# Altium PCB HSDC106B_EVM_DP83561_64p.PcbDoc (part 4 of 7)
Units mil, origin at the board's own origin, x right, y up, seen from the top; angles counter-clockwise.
Board outline 8750.24 x 6394.7 mil, 6 copper layers (Top Layer, GND1, SIG1, SIG2, GND2, Bottom Layer), stack 60.4 mil thick; 472 components, 324 nets, 1622 pads, 1086 vias.
Unrouted connection lines stored in the file: 1.
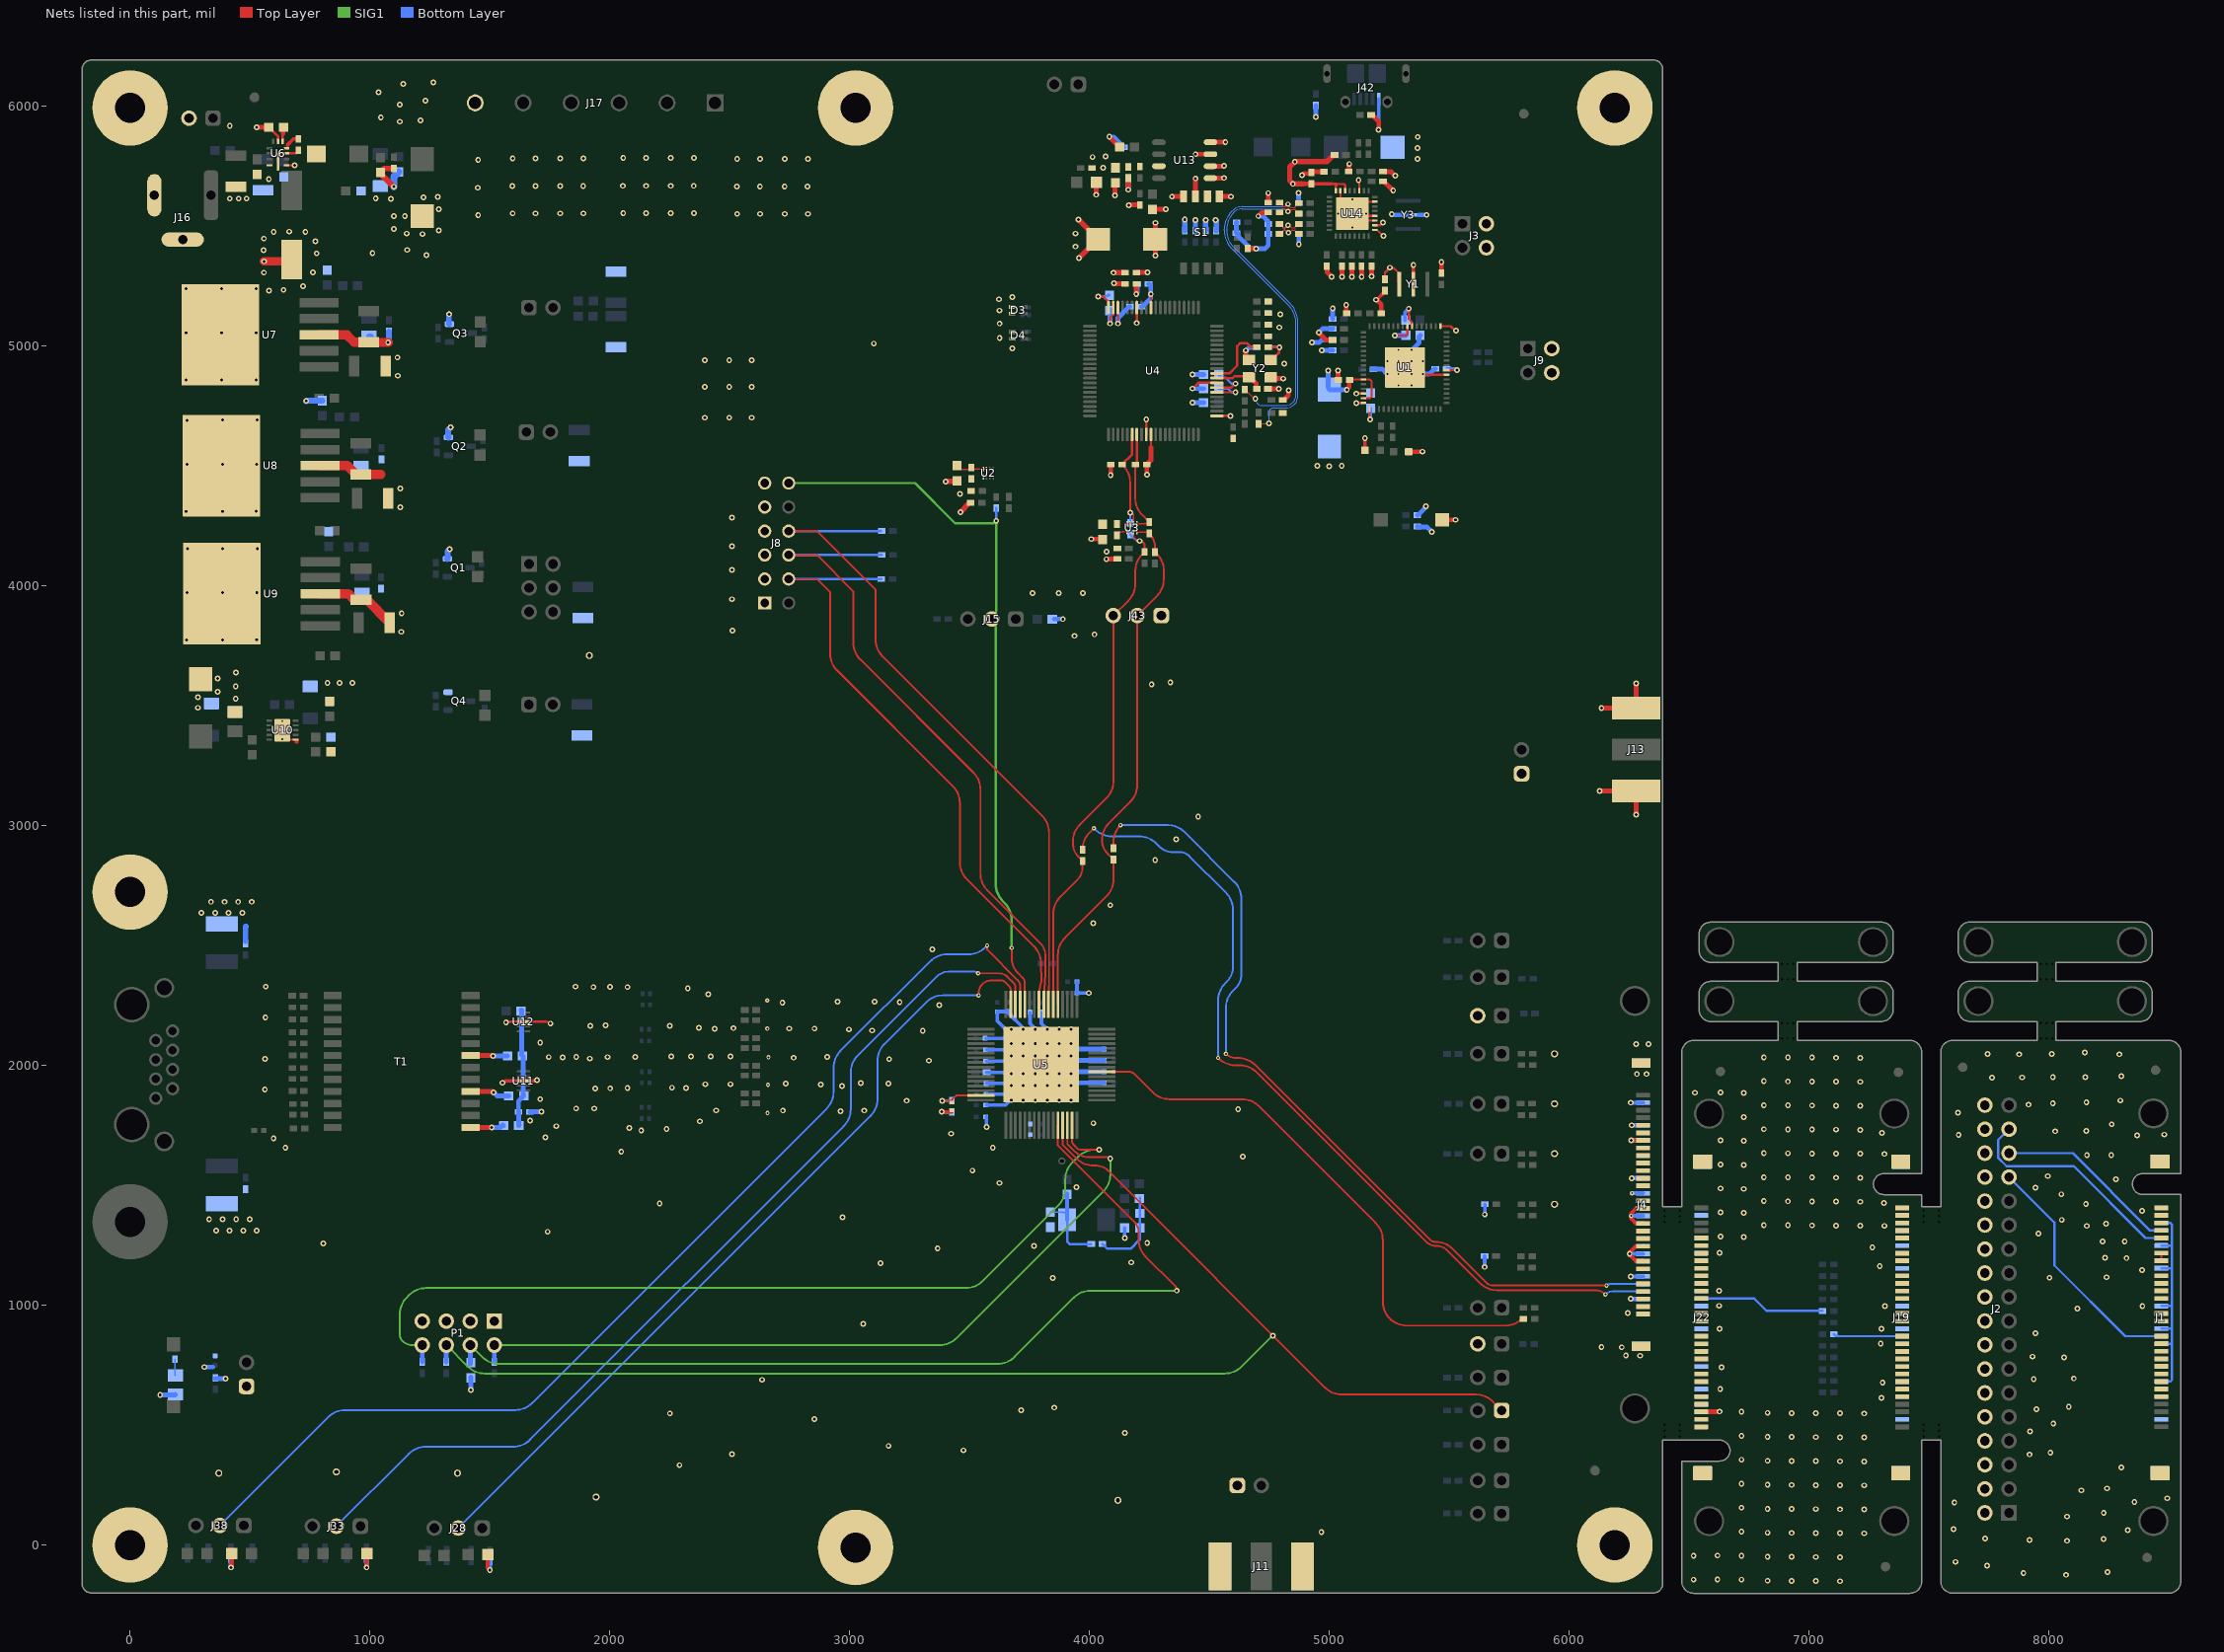
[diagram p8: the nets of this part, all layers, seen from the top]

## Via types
v1: diameter 24, hole 12, Top Layer to Bottom Layer, tented both sides, 903 vias
v2: diameter 24, hole 12, Top Layer to Bottom Layer, 65 vias
v3: diameter 18, hole 7.87, Top Layer to Bottom Layer, tented both sides, 53 vias
v4: diameter 22, hole 10, Top Layer to Bottom Layer, tented both sides, 43 vias
v5: diameter 19.68, hole 7.87, Top Layer to Bottom Layer, 21 vias
v6: diameter 22, hole 12, Top Layer to Bottom Layer, tented both sides, 1 vias

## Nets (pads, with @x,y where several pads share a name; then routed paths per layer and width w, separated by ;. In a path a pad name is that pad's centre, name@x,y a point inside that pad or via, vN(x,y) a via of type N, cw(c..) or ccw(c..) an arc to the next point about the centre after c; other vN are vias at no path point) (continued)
GND: C1.2 C2.2 C3.2 C4.2 C5.2 C6.2 C7.2 C8.2 C9.2 C10.2 C11.2 C12.2 C13.2 C14.2 C15.2 C16.2 C17.2 C18.2 C19.1 C20.2 C21.2 C22.2 C23.2 C24.2 C25.2 C26.1 C27.2 C28.1 C29.1 C30.1 C31.1 C32.1 C33.1 C34.1 C35.1 C36.1 C37.1 C38.1 C39.1 C40.1 C41.1 C42.1 C43.1 C44.1 C45.1 C46.1 C47.2 C48.2 C49.2 C50.2 C51.1 C52.2 C53.2 C55.2 C57.2 C58.1 C59.1 C60.1 C61.1 C62.2 C63.2 C64.2 C65.2 C66.2 C67.2 C68.2 C70.2 C71.2 C73.2 C74.1 C75.1 C76.1 C77.1 C78.2 C80.2 C81.2 C83.2 C84.1 C85.1 C86.1 C87.2 C88.1 C91.2 C92.1 C93.2 C94.2 C108.1 C109.1 C110.2 C111.2 C112.2 C113.2 C114.2 C115.2 C116.2 C117.1 C118.2 C119.2 C120.2 C121.2 C122.2 C123.2 C124.2 C125.2 C126.2 C127.2 C128.2 C129.2 D1.1 D2.1 D3.3 D3.4 D4.3 D4.4 J3.2 J3.4 J4.1 J4.3 J4.5 J4.6 J4.7 J4.9 J4.12 J4.13 J4.15 J4.18 J4.19 J4.21 J4.23 J4.25 J4.28 J4.29 J4.31 J4.34 J4.35 J4.37 J4.38 J4.39 J4.41 J4.43 J4.45 J4.47 J4.48 J4.49 J4.51 J4.52 J4.58 J4.MP1 J4.MP2 J4.MP3 J4.MP4 J5.2 J6.2 J8.1 J8.3 J8.5 J8.7 J8.9 J8.11 J9.2 J9.4 J10.1 J11.2 J11.3 J11.4 J11.5 J12.1 J13.2 J13.3 J13.4 J13.5 J14.1 J16.2 J16.3 J17.6 J18.2 J42.5 J43.1 LD2.2 LD4.2 LD6.2 LD7.2 M1.1 M2.1 M3.1 M4.1 M5.1 M6.1 M7.1 P1.1 P1.3 P1.5 P1.7 Q1.2 Q2.2 Q3.2 Q4.2 R5.1 R6.1 R30.1 R35.1 R37.1 R58.1 R59.1 R60.1 R61.1 R74.2 R79.2 R83.2 R90.1 R91.1 R94.1 R95.1 R98.1 R101.1 R126.1 R145.2 R146.2 R150.1 R154.1 R158.1 R162.1 R171.1 R176.1 R177.2 R186.1 R187.1 R188.1 R189.1 R190.1 R191.1 R194.1 R195.1 R200.1 S1.5 S1.6 S1.7 S1.8 S2.1 TP1.1 TP2.1 TP3.1 TP4.1 TP5.1 TP6.1 TP7.1 TP8.1 TP9.1 TP10.1 U1.14 U1.16 U1.39 U1.49 U1.56 U1.65 U2.1 U3.1 U4.14 U4.19 U4.49 U4.61 U4.68 U5.65 U6.1 U6.6 U6.11 U7.3 U7.6 U8.3 U8.6 U9.3 U9.6 U10.6 U10.11 U11.3@1624.13,1936.31 U11.8@1657,1936.31 U12.3@1624.13,2182.31 U12.8@1657,2182.31 U13.5 U13.6 U13.7 U13.8 U14.7 U14.27 U14.28 U14.31 U14.33 Y1.2 Y2.2 Y2.4 Y3.2 | length 11470.1
  Top Layer w6: C14.2@4114.6,4210.98 4114.6,4214.92 4123.41,4223.73 4134.18,4223.73 4137.3,4226.86 U3.1@4155.93,4226.86
  Top Layer w9: U10.11@635,3398.7 635,3388.7 664,3359.7 689.75,3359.7 U10.6@690.12,3359.33 690.12,3347.58 691.58,3346.12 699.02,3346.12 ; 699,3346.14 U10.6@699,3358.7 ; U14.7@5046.2,5647.99 5046.2,5602.72 v5(5095.41,5553.5) ; v1(5112.36,4763.06) U1.16@5142.77,4763.06 ; v1(5113.27,4802.43) U1.14@5142.77,4802.43 ; U14.27@5189.9,5523.98 5124.94,5523.98 U14.33@5105.25,5543.66 ; U14.28@5189.9,5543.66 U14.33@5105.25,5543.66 ; U14.31@5189.9,5602.72 5144.62,5602.72 v5(5095.41,5553.5) ; v1(5273.51,5044.52) 5320.56,5044.52 5325.84,5049.8 U1.56@5325.84,5083.92 ; U1.65@5315.99,4910.69 5345.52,4881.17 U1.39@5489.22,4881.17 ; U1.49@5463.63,5083.92 5505.74,5083.92 5524.96,5064.7 v1(5527.96,5064.7) ; v5(5095.41,5553.5) U14.33@5105.25,5543.66
  Top Layer w10: C62.2@577.61,5913.61 578.59,5913.61 616.52,5875.68 616.52,5853.8 U6.6@616.6,5853.72 ; U6.1@652.03,5754.31 652.11,5754.39 685.39,5754.39 v1(685.6,5754.61) ; v1(1567.72,2180.31) cw(c1572.57,2175.46) 1572.57,2182.32 U12.3@1624.13,2182.31 U12.8@1657,2182.31 1735.34,2182.31 cw(c1735.34,2157.34) v1(1753,2175) ; v1(4085.85,5094.61) 4085.85,5118.41 4099.15,5131.72 U4.19@4099.15,5161.23 U4.19@4098.24,5160.32 ; U4.14@4197.57,5161.23 v1(4197.6,5096.61) ; U4.49@4236.94,4631.7 v1(4236.94,4695.24) ; v1(4429.46,4823.24) 4453.47,4847.25 U4.68@4531.24,4847.25
  Top Layer w11: U4.61@4531.24,4709.46 v1(4587.79,4709.46)
  Top Layer w15: v1(1552,1927.68) cw(c1572.83,1906.85) 1572.83,1936.32 U11.3@1624.13,1936.31 U11.8@1657,1936.31 1696.23,1936.31 v1(1696.23,1938.66) ; v1(3383.6,1807.95) 3385.57,1805.98 C51.1@3426.41,1805.98 ; D1.1@5148.79,4565.7 v1(5148.79,4616.8) ; v1@5197.57,5193.46 5232.1,5227.99 C4.2@5232.1,5231.93 ; Y1.2@5350.6,5258.61 v1(5350.6,5338.61)
  Top Layer w17: v1(420.5,-93.25) 423.66,-90.09 LD6.2@423.66,-35 ; v1(986,-93.25) 986.84,-92.41 LD4.2@986.84,-35 ; LD2.2@1491.34,-40 1491.34,-96.19 v1(1500,-104.85) ; v3(6258.23,1372.76) 6258.42,1372.56 6258.42,1362.21 6278.03,1342.6 6307.52,1342.6 J4.25@6308.86,1341.26 ; 6258.42,1383.31 6278.03,1402.91 6307.52,1402.91 J4.29@6308.86,1404.25 ; v1(6258.65,1688.01) J4.47@6306.56,1688.01 ; J4.15@6308.86,1183.78 6307.52,1185.12 6278.03,1185.12 6253.27,1209.88 6253.27,1213.94 v1(6251.93,1215.28) 6253.27,1216.62 6253.27,1220.67 6278.03,1245.43 6307.52,1245.43 J4.19@6308.86,1246.77
  Top Layer w20: v1(527.6,5912.61) 528.1,5913.11 577.11,5913.11 C62.2@577.61,5913.61 ; v1(4028.2,5631.61) 4028.57,5631.98 4028.57,5682.33 LD7.2@4028.94,5682.7 ; v1(4082.6,5873.61) 4082.6,5872.62 4124.52,5830.7 C111.2@4125.5,5830.7 ; v1(4106.6,5628.61) 4107.1,5629.11 4107.1,5680.61 C114.2@4107.6,5681.11 ; v1(4161.6,5652.62) C112.2@4161.6,5700.64 ; v1(4164.5,5587.94) 4165.58,5587.94 4166.96,5589.31 R176.1@4210,5589.31 ; C23.2@4195.41,5259.61 4195.5,5259.51 4195.5,5217.7 v1(4195.6,5217.61) ; C22.2@4195.41,5306.61 4195.91,5307.11 4241.1,5307.11 v1(4241.6,5307.61) ; C115.2@4263.6,5570.61 v1(4318.41,5570.61) v1@4320.92,5568.11 ; v1(4274.69,5378.31) C21.2@4274.69,5445.61 v1(4274.69,5514.69) ; v1(4344.17,5623.72) 4344.66,5624.21 4391.51,5624.21 S1.8@4392,5624.7 ; S1.7@4442,5624.7 4442.3,5625 4442.3,5699.31 v1(4442.6,5699.61) ; v1(4442.6,5800.61) 4442.65,5800.65 4504.24,5800.65 U13.7@4504.28,5800.7 ; U13.5@4504.28,5700.7 4504.74,5701.15 4561.15,5701.15 v1(4561.6,5701.61) ; U13.6@4504.28,5750.7 4557.61,5750.7 4559.52,5752.61 v1(4560.6,5752.61) ; U13.8@4504.28,5850.7 4504.74,5851.15 4566.15,5851.15 v1(4566.6,5851.61) ; S1.5@4542,5624.7 4542.49,5624.21 4589.74,5624.21 v1(4590.23,5623.72) ; v1(4652.27,4981.94) 4652.27,4953.69 4663.92,4942.04 Y2.2@4665.32,4942.04 ; R200.1@4659.87,5407.15 v1(4694.87,5407.15) ; v6(4704,5542.7) 4718.8,5557.5 R186.1@4745.38,5557.5 ; C15.2@4744.6,4822.61 v1(4789.6,4822.61) ; R187.1@4745.38,5598.72 v1(4745.38,5638.38) ; Y2.4@4755.87,4871.17 4761.68,4865.37 4807.83,4865.37 v1(4808.6,4864.61) ; C123.2@4806.22,4775.61 4810.16,4775.61 4829.83,4795.28 4829.83,4814.98 v1(4830.6,4815.74) ; v1(4886,5713) 4887.08,5713 4894.47,5720.39 4923.19,5720.39 4925,5722.2 C129.2@4925,5724.32 ; C129.2@4925,5727.7 C126.2@4977.38,5727.7 ; v1(4956.03,5056.7) 4987.03,5025.7 C3.2@5017.03,5025.7 ; C11.2@5036.38,4859.7 v1(5036.38,4898.08) ; R188.1@5053.44,5335.66 5053.6,5335.51 v1(5053.6,5289.61) ; C118.2@5082.35,5727.49 5082.35,5759.13 v1(5083,5759.79) ; v1(5094.25,5289.75) R189.1@5094.25,5333.98 ; v1(5134.6,5289.4) R190.1@5134.6,5333.98 ; v1(5176.79,5290.9) 5176.22,5291.47 5176.22,5310.86 5176.41,5311.05 5176.41,5333.61 R191.1@5176.79,5333.98 ; C117.1@5180.41,5962.69 5206.02,5937.09 5206.02,5904.62 5205.18,5903.78 v1(5205.18,5902.7) ; v1@5197.57,5193.46 5216.62,5174.41 C8.2@5216.62,5136.7 ; C119.2@5223.62,5687 5227.56,5687 5264.89,5649.67 v1(5266.22,5649.67) ; D2.1@5331.18,4560.04 v1(5388.26,4560.04) ; C5.2@5467.6,5305.23 v1(5467.6,5351.6) ; S2.1@5470.95,4275.7 v1(5526,4275.7) ; v1(6127.61,3145.61) J13.3@6279.6,3145.61 v1(6279.6,3045.6) ; v1(6134.61,3490.61) J13.2@6279.6,3490.61 v1(6279.6,3593.4)
  Top Layer w23: C61.1@1058.87,5740.37 C59.1@1098.85,5740.37
  Top Layer w25: C61.1@1043.6,5724.11 1049.8,5717.91 1049.8,5714.73 v1(1099.47,5665.06) ; C61.1@1043.6,5725.09 C61.1@1058.87,5740.37
  Top Layer w35: v1@558.68,5353.61 666.3,5353.61 C63.2@674.6,5361.91
  Top Layer w38: U7.3@788.42,5047.7 904,5047.7 905,5046.7 ; 904,5046.7 934,5016.7 C52.2@977,5016.7 ; C52.2@995,5015.74 v1(1076.04,5015.74)
  Top Layer w40: U8.3@792.42,4501.7 906,4501.7 C70.2@942,4465.7 ; U9.3@793.42,3967.7 910,3967.7 C80.2@934,3943.7 ; C70.2@962,4464.74 1045.04,4464.74 ; C80.2@963,3942.74 985.92,3942.74 C78.2@1081.96,3846.7
  Bottom Layer w10: C36.1@3615.74,2224.29 C36.1@3616.37,2224.92 ; v1@4693.02,5408.99 v1(4694.87,5407.15)
  Bottom Layer w15: v1(3383.6,1807.95) 3384.58,1806.97 3425.43,1806.97 R83.2@3426.41,1805.98 ; C33.1@3569.22,2113.61 3648.66,2113.61 3671.56,2090.7 3671.56,2088.26 3648.91,2065.61 C26.1@3570.22,2065.61 ; v1(3570.87,1743.87) C38.1@3570.87,1786.1 ; C39.1@3570.87,1834.92 3650.78,1834.92 3671.56,1855.7 v2(3674,1855.7) 3649.09,1880.61 C35.1@3572.22,1880.61 ; C27.2@3571.22,1971.61 3665.66,1971.61 3671.56,1965.7 v2(3674,1965.7) ; C28.1@3571.22,2018.61 3649.47,2018.61 3671.56,2040.7 v2(3674,2040.7) ; C34.1@3571.41,1925.61 3661.66,1925.61 3671.56,1915.7 v2(3674,1915.7) ; C36.1@3615.74,2219.08 3615.74,2185.82 3649.14,2152.42 3672.28,2152.42 v2(3674,2150.7) ; C36.1@3616.37,2224.92 C37.1@3663.6,2224.92 ; C37.1@3663.6,2220.98 3663.6,2217.05 3722.28,2158.37 3722.28,2152.42 v2(3724,2150.7) ; C44.1@3752.6,2218.98 3752.6,2174.54 3774,2153.14 v2(3774,2150.7) ; C45.1@3799.6,2218.98 3799.6,2175.1 v2(3824,2150.7) ; C32.1@3948.1,2302.41 C31.1@3948.1,2349.36 ; C32.1@3952.04,2302.41 v1(3997.8,2302.41) ; C49.2@4146.98,1322.8 4146.98,1280.83 v1(4147.46,1280.34) ; v1@5204,5902.7 v1(5205.18,5902.7) 5206.02,5903.54 J42.5@5206.02,6031.3 ; v1(5647.85,1159.98) R154.1@5647.85,1205.42 ; v1(5648.39,1378.61) R158.1@5648.39,1421.22
  Bottom Layer w17: v1(6251.93,1215.28) J4.18@6308.86,1215.28 ; v1(6256.2,1845.2) J4.58@6308.86,1845.2 J4.58@6308.96,1845.1 ; v1(6256.49,1026.93) 6257.12,1026.3 J4.6@6308.86,1026.3 ; v1@6256.57,1121.41 v1(6257.2,1120.79) J4.12@6308.86,1120.79 ; v3(6258.23,1372.76) J4.28@6308.86,1372.76 ; v1(6258.65,1688.01) 6258.79,1687.86 6308.71,1687.86 J4.48@6308.86,1687.72 ; v1(6260.29,1750.71) J4.52@6308.86,1750.71 ; v3(6262,1467.24) J4.34@6308.86,1467.24
  Bottom Layer w18: v1@6260.44,1530.24 J4.38@6308.86,1530.24
  Bottom Layer w20: v1(125.6,626.61) 188.09,626.61 C47.2@189.29,627.8 ; v1(309.67,742.6) 345.9,742.6 ; R79.2@355.45,694.45 v1(397.5,694.45) ; v1(420.5,-93.25) R171.1@420.5,-57.02 ; v1(986,-93.25) R162.1@986,-57.02 ; v1(1420.6,646.61) R91.1@1420.6,698.11 R91.1@1420.6,701.32 ; v1(1500,-104.85) R150.1@1500,-68.62 ; R126.1@1666.62,1806 1667.62,1807 v1(1715,1807) ; R90.1@3852.93,3861.93 v1(3889.15,3861.93) ; v2(3924,1915.7) 3935.91,1927.61 C43.1@4061.91,1927.61 ; v2(3924,1965.7) 3932,1973.7 C42.1@4061.75,1973.7 ; v2(3924,2040.7) 3942.94,2021.76 C29.1@4061.75,2021.76 ; v2(3924,2090.7) 3946.09,2068.61 C30.1@4060.91,2068.61 ; v1(4082.6,5873.61) 4083.36,5872.84 4100.74,5872.84 4138.23,5835.35 4138.23,5831.42 4140.04,5829.61 C110.2@4143.98,5829.61 ; v1(4085.85,5094.61) 4085.85,5148.17 C18.2@4090.38,5152.7 ; v1(4161.6,5652.62) C113.2@4161.6,5700.64 ; v1(4195.6,5217.61) 4195.6,5218.69 4199.38,5222.47 C24.2@4199.38,5259.61 ; v1(4429.46,4764.18) C19.1@4476.46,4764.18 ; v1(4429.46,4823.24) C20.2@4475.77,4823.24 C20.2@4476.46,4823.24 ; v1(4429.79,4881.61) C17.2@4476.79,4881.61 ; C128.2@4614,5516.7 4613.31,5516.01 4613.31,5472.39 C127.2@4612.62,5471.7 4616.56,5471.7 4618.37,5469.89 4618.37,5460.36 4669.74,5408.99 v1@4693.02,5408.99 ; v1(4652.27,4981.94) 4653.35,4981.94 4665.21,4993.8 4696.17,4993.8 C16.2@4697.98,4995.61 ; v1(4694.87,5407.15) 4732.14,5407.15 4745.38,5420.39 4745.38,5519.83 4722.5,5542.7 v6(4704,5542.7) ; C121.2@4872.35,5596.61 v1(4872.35,5639.65) ; v1(4872.79,5425) C124.2@4872.79,5468.5 ; v1(4944,5955.9) R177.2@4944,6004.08 ; v1(4956.03,5056.7) 4971.94,5072.61 R5.1@5013.98,5072.61 ; v1(4968,4982.7) R6.1@5013.98,4982.7 ; C2.2@5013.98,5113.61 5014.33,5113.96 5014.33,5156.74 v1(5014.68,5157.09) ; C1.2@5178.24,4904.7 5220.81,4904.7 v5(5242.18,4883.33) ; v1(5260.13,5551.15) 5261.22,5551.15 5265.02,5547.35 Y3.2@5329.46,5547.35 ; v1(5273.51,5044.52) C6.2@5318.01,5044.52 ; v5(5343.36,4984.51) 5343.51,4984.51 5374.43,5015.43 5374.43,5040.24 C9.2@5379.61,5045.43 ; C25.2@5366.62,4247.61 5368.43,4245.8 5408.16,4245.8 v1(5428,4225.95) ; Y3.2@5374,5547.7 v1(5406,5547.7) ; v5(5389.81,4883.33) 5415.76,4883.33 5438.04,4905.61 C12.2@5441.98,4905.61 ; v1(6279.6,3045.6) J13.4@6279.6,3145.61 ; J13.5@6279.6,3490.61 v1(6279.6,3593.4)
  Bottom Layer w22: R146.2@482,2517.26 482,2579.64 483,2580.64 ; v1(1330.6,5133.61) 1329.74,5132.75 1329.74,5092.91 1330.55,5092.1 Q3.2@1331.76,5092.1
  Bottom Layer w25: v1(734.6,4771.61) 735.68,4772.69 R98.1@801,4772.69 ; C53.2@996.6,5039.61 1003.1,5039.61 1026.97,5015.74 v1(1076.04,5015.74) 1079.6,5019.3 C55.2@1079.6,5060.98 ; Q1.2@1322.76,4113.1 1322.91,4113.1 1323.6,4113.79 1323.6,4144.3 v1(1333,4153.7) ; Q2.2@1327.16,4619.5 1327,4619.66 1327,4651.7 v1(1337,4661.7)
  Bottom Layer w30: v1(1099.47,5665.06) 1099.47,5706.12 C58.1@1120.1,5726.75
  other v1: 4967.35,54.61 2290.63,333.33 2508.93,379.28 3474,395 3162.6,413.61 4148.11,467.59 2852.71,525.68 2251,549 3715.6,562.61 3853.6,573.61 2634.65,689.24 6296,790 6237,791 6219,825 6134.6,825.61 3056.6,923.13 6244,967.6 3847.6,1113.61 3129.37,1175.9 4174.5,1178.75 3366.82,1237.18 3769,1248 805.58,1258.11 4240.88,1260.12 1740.78,1306.69 358.65,1311.96 415.14,1311.96 471.64,1311.96 528.13,1311.96 329.42,1359.07 385.91,1359.07 442.4,1359.07 498.89,1359.07 2971,1367 2208,1425 3945.35,1492.35 3624.48,1510.16 6260.6,1529.61 3512.41,1561.73 4640,1619.83 2047.81,1640.29 648,1657 3597,1657.87 598.6,1696.61 1732,1701 3423,1715.74 2131.55,1729.72 2236.89,1735.68 2081,1739 1777,1747 4016.68,1759.34 2376.08,1767.36 1668,1770 2962.17,1808.94 2443.43,1812.7 2722.19,1812.4 3061.29,1812.4 4619.94,1817.61 1860,1821 1936,1821 3237.52,1853.46 1710,1860 562,1900.55 1939,1904 2002,1905 2074,1905.95 2318.01,1906.48 2259.47,1907.61 2968.6,1914.61 2879.42,1920.49 2398.51,1921.89 2503.03,1922.01 2733.99,1924.42 3162.11,1924.42 3046.47,1926.39 6282.6,1964.61 6322.6,1964.61 3330.99,2020.57 3164.9,2026.72 563,2027.92 1917,2029 2767.4,2032.51 1803.74,2034.01 1745.19,2035.14 1990.69,2035.14 1860.21,2035.67 2105.71,2035.67 2906.93,2036.44 2256.72,2038.33 2338.82,2038.33 2420.92,2038.33 2503.03,2038.33 6280,2089 6331,2090 1710,2095 3305,2144.46 3093.31,2146.05 2997.06,2150.33 2437.41,2153.05 2747.74,2154.36 2853.87,2154.36 2516,2156 2371.43,2157.2 1919,2166 2250,2166 1983,2168 564,2199.9 3373.6,2252.61 2720.23,2262.45 3208.34,2264.06 2949.33,2266.72 3104.86,2266.72 2410.06,2297.41 2325.2,2321.41 1932,2327 2074,2327 2001,2328 566,2329 1857,2329 3345.6,2484.59 4016,2593.7 298,2637.33 354.49,2637.33 410.98,2637.33 467.48,2637.33 4087,2668.7 337.54,2682.81 394.03,2682.81 450.52,2682.81 507.01,2682.81 4274,2856.7 4362,2943.7 4453,3037.7 283.6,3492.09 440.39,3529.7 283.6,3535.61 365.6,3558.61 440.39,3581.7 4259.41,3589.28 823,3595.7 874,3595.7 927,3595.7 4337.58,3597.82 364.6,3613.61 441.39,3638.7 3937.88,3791.92 4020.93,3798.15 1131,3808.7 2512,3813.7 1132,3885.7 2510,3944.7 3763,3969.7 3872,3970.7 3972,3970.7 2510,4066.7 4071.6,4143.61 2510,4165.7 2509,4285.7 1127,4327.7 3459.92,4384.32 1127,4406.7 5000,4499.7 4950,4500.7 5052,4500.7 2396.29,4701.86 2498.29,4701.86 2591.29,4701.86 2396.29,4829.86 2498.29,4829.86 2591.29,4829.86 1116,4876.7 4811.6,4927.61 2396.29,4941.86 2498.29,4941.86 2591.29,4941.86 1115,4952.7 3678.98,4990.61 3101,5010.7 3625.6,5033.61 3625.6,5094.61 3624.6,5148.61 5195.31,5193.46 3622.6,5195.61 3678.6,5205.61 579.83,5232.18 639.83,5234.89 720.83,5250.89 557.83,5306.89 763.02,5308.13 558.91,5353.89 1236,5379.7 777.83,5386.89 1010.6,5388.61 556.5,5400.47 1155.6,5401.61 772.83,5437.89 557.83,5448.89 1219.78,5467.61 1154.06,5469.61 598.83,5476.89 730.83,5476.89 663.83,5477.89 1287.76,5482.47 1099.6,5489.21 1146,5542 1099.6,5542.21 1451,5546.7 2531,5551.7 2627,5551.7 2730,5551.7 2826,5551.7 1595,5553.7 1691,5553.7 1794,5553.7 1890,5553.7 2056,5554.7 2152,5554.7 2255,5554.7 2351,5554.7 1287.6,5571.61 1087.75,5614.56 415.6,5615.61 452.6,5615.61 485.6,5615.61 1024.6,5616.61 1223.6,5620.61 1283.6,5622.61 1450,5660.7 2530,5665.7 2626,5665.7 2729,5665.7 2825,5665.7 1594,5667.7 1690,5667.7 1793,5667.7 1889,5667.7 2055,5668.7 2151,5668.7 2254,5668.7 2350,5668.7 578.51,5696.79 1451,5776.7 2531,5781.7 2627,5781.7 2730,5781.7 2826,5781.7 5368,5781.7 1595,5783.7 1691,5783.7 1794,5783.7 1890,5783.7 2056,5784.7 2152,5784.7 2255,5784.7 2351,5784.7 5368,5826.7 5369,5872.7 415.6,5919.61 1124.6,5936.61 1210.48,5942.17 1045.6,5953.61 1124.87,6007.23 1231.6,6024.61 1035.6,6058.61 1138.6,6093.61 1264.6,6099.61
  other v2: 3724,1855.7 3774,1855.7 3824,1855.7 3874,1855.7 3924,1855.7 3724,1915.7 3774,1915.7 3824,1915.7 3874,1915.7 3724,1965.7 3774,1965.7 3824,1965.7 3874,1965.7 3724,2040.7 3774,2040.7 3824,2040.7 3874,2040.7 3674,2090.7 3724,2090.7 3774,2090.7 3824,2090.7 3874,2090.7 3874,2150.7 3924,2150.7 235,3774.7 386,3774.7 527,3775.7 238,3971.7 386,3971.7 529,3971.7 239,4154.7 386,4155.7 531,4155.7 234,4310.7 385,4310.7 526,4311.7 237,4507.7 385,4507.7 528,4507.7 238,4690.7 385,4691.7 530,4691.7 234,4858.7 382,4858.7 525,4858.7 234,5055.7 382,5055.7 525,5055.7 234,5239.7 382,5239.7 525,5239.7
  other v3: 2657.7,1801.7 2659.93,1919.7 2661.87,2034.35 2656.94,2153.7 2656.81,2271.53
  other v5: 635,3361.3 612.36,3398.7 657.64,3398.7 635,3436.1 5288.63,4836.87 5343.36,4836.87 5288.63,4883.33 5343.36,4883.33 5242.18,4938.06 5288.63,4938.06 5343.36,4938.06 5389.81,4938.06 5288.63,4984.51 5095.41,5495.43 5037.34,5553.5 5153.48,5553.5 5095.41,5611.58
GND_1: J1.1 J1.3 J1.5 J1.6 J1.7 J1.9 J1.12 J1.13 J1.15 J1.18 J1.19 J1.21 J1.23 J1.25 J1.28 J1.29 J1.31 J1.34 J1.35 J1.37 J1.38 J1.39 J1.41 J1.43 J1.45 J1.47 J1.48 J1.49 J1.51 J1.52 J1.58 J1.MP1 J1.MP2 J1.MP3 J1.MP4 J2.2 J2.4 J2.6 J2.8 J2.10 J2.12 J2.14 J2.16 J2.18 J2.20 J2.22 J2.24 J2.26 J2.28 J2.30 J2.32 J2.34 J2.36 | length 992.3
  Top Layer w10: J1.15@8469.11,1186.22 8469,1186.22 8469,1217.72 J1.13@8469.11,1217.72
  Bottom Layer w10: J1.48@8469.11,682.28 8470.11,683.29 8507.14,683.29 8513,689.15 8513,839.76 ; J1.38@8469.11,839.76 8513,839.76 ; J1.34@8469.11,902.76 8513,902.76 ; J1.28@8469.11,997.24 8509,997.24 8513,997.24 ; J1.18@8469.11,1154.72 8513,1154.72 ; J1.12@8469.11,1249.21 8513,1249.21 ; J1.6@8469.11,1343.7 8470.11,1342.7 8507.14,1342.7 8513,1336.84 8513,1249.21 ; 8513,839.76 8513,902.76 ; 8513,902.76 8513,997.24 ; 8513,997.24 8513,1154.72 ; 8513,1154.72 8513,1249.21
  other v1: 8072,-124 7894,-116 8244,-113 7742,-86 7611,-70 8076,18 7919,21 8228,26 7735,28 8329,62 7602.74,66.06 8076,119 8229,134 7606,177 8357,180 8494,195 8135,228 8242.61,236.36 8302,324 7919,378 8006.81,384.89 7922,474 8019,507 7948,567 8083,577 7937,692 8104,695 8064,782 7932,786 7944,883 8119,986 8390.02,997.06 8002.98,1114.97 8241,1117 8389.33,1146.67 8324,1197 8234,1198 8224,1266 8316,1266 7957,1299 8158,1331 8238,1341 8054,1356 8389.14,1393.97 8154.9,1422.92 8052.34,1463.12 7944.23,1490.84 8280,1526 7996,1539 8260,1626 8159,1627 8368,1709 7624,1711 8481,1712 8027,1726 8156,1727 8262,1755 7621,1804 7915,1837 8017,1842 8157,1847 8298,1854 7763,1950 7888.55,1950.48 8017,1952 8152,1952 8302,1955 7876,2047 8294,2047 7744.45,2048.06 8012,2048 8150,2054
GND_2: J19.1 J19.3 J19.5 J19.6 J19.7 J19.9 J19.12 J19.13 J19.15 J19.18 J19.19 J19.21 J19.23 J19.25 J19.28 J19.29 J19.31 J19.34 J19.35 J19.37 J19.38 J19.39 J19.41 J19.43 J19.45 J19.47 J19.48 J19.49 J19.51 J19.52 J19.58 J19.MP1 J19.MP2 J19.MP3 J19.MP4 J22.1 J22.3 J22.5 J22.6 J22.7 J22.9 J22.12 J22.13 J22.15 J22.18 J22.19 J22.21 J22.23 J22.25 J22.28 J22.29 J22.31 J22.34 J22.35 J22.37 J22.38 J22.39 J22.41 J22.43 J22.45 J22.47 J22.48 J22.49 J22.51 J22.52 J22.58 J22.MP1 J22.MP2 J22.MP3 J22.MP4 | length 76.8
  Top Layer w20: J22.5@6550.68,555.91 6624.82,555.91 6625.92,557 v1(6627,557)
  other v1: 7028.81,-149.85 7129.41,-150.46 6928.2,-149.23 6827.6,-148.62 6518.91,-144.09 6718.91,-144.09 6618.3,-143.48 7028.81,-49.85 7129.41,-50.46 6928.2,-49.23 6827.6,-48.62 6518.91,-44.09 6718.91,-44.09 6618.3,-43.48 7230.01,48.92 7028.81,50.15 7129.41,49.54 6928.2,50.77 6827.6,51.38 6718.91,55.91 7230.01,148.92 7028.81,150.15 7129.41,149.54 6928.2,150.77 6827.6,151.38 6718.91,155.91 7230.01,248.92 7028.81,250.15 7129.41,249.54 6928.2,250.77 6827.6,251.38 6718.91,255.91 7230.01,348.92 7028.81,350.15 7129.41,349.54 6928.2,350.77 6827.6,351.38 6718.91,355.91 7230.01,448.92 7028.81,450.15 7129.41,449.54 6928.2,450.77 6827.6,451.38 6718.91,455.91 7230.01,548.92 7028.81,550.15 7129.41,549.54 6928.2,550.77 6827.6,551.38 6718.91,555.91 7302,614 6630,650.39 7307,678 6635,741 7299,840 7302,902 6627,902.36 7317,997 6625,998 6625,1060 7295,1163 6627,1219 7264,1241 6727.67,1285.44 6631.7,1287.49 7214.01,1331.92 7314.61,1331.31 7012.81,1333.15 7113.41,1332.54 6912.2,1333.77 6811.6,1334.38 6727.67,1385.44 6631.7,1387.49 7312.22,1426.68 7214.01,1431.92 7012.81,1433.15 7113.41,1432.54 6912.2,1433.77 6811.6,1434.38 6727.67,1485.44 6631.7,1487.49 7214.01,1531.92 7012.81,1533.15 7113.41,1532.54 6912.2,1533.77 6811.6,1534.38 6727.67,1585.44 6631.7,1587.49 7214.01,1631.92 7314.61,1631.31 7012.81,1633.15 7113.41,1632.54 6912.2,1633.77 6811.6,1634.38 6727.67,1685.44 6631.7,1687.49 7304,1719 7214.01,1731.92 7012.81,1733.15 7113.41,1732.54 6912.2,1733.77 6811.6,1734.38 6727.67,1785.44 7214.01,1831.92 7012.81,1833.15 7113.41,1832.54 6912.2,1833.77 6811.6,1834.38 6727.67,1885.44 6524.02,1886.54 6631.7,1887.49 7214.01,1931.92 7012.81,1933.15 7113.41,1932.54 6912.2,1933.77 6811.6,1934.38 7214.01,2031.92 7012.81,2033.15 7113.41,2032.54 6912.2,2033.77 6811.6,2034.38
GTX_CLK: R20.1 U5.39 | length 2371.9
  Top Layer w8: U5.39@4051.41,1973.7 4165.99,1973.7 cw(c4165.99,1944.14) 4186.9,1965.04 4262.84,1889.1 ccw(c4333.55,1959.81) 4333.55,1859.81 4635.6,1859.81 cw(c4635.6,1759.81) 4706.32,1830.52 5193.64,1343.2 cw(c5122.92,1272.49) 5222.92,1272.49 5222.92,1015.42 ccw(c5322.92,1015.42) 5322.92,915.42 5735.34,915.42 ccw(c5735.34,1008.75) R20.1@5801.34,942.76
GTX_CLK_1: J1.36 J2.29 | length 1014.5
  Bottom Layer w10: J2.29@7833.6,1534.61 8023.6,1344.61 8023.6,1166.61 8318.94,871.26 J1.36@8469.11,871.26
GTX_CLK_2: J22.36 R202.1 | length 527.8
  Bottom Layer w10: J22.36@6550.68,1028.35 6551.29,1027.73 6772.47,1027.73 6823.78,976.42 R202.1@7056.98,976.42
GTX_CLK_LP: J19.36 R201.2 | length 287.8
  Bottom Layer w10: R201.2@7104.22,879.33 7111.03,872.52 7119.48,872.52 7120.83,871.17 J19.36@7388.6,871.17
HUB_D1_N: R180.2 R184.1 R187.2 | length 1498.5
  Top Layer w5: R180.2@4648,4819.32 4682.82,4784.5 ccw(c4692,4793.68) v1(4692,4780.7) ; R187.2@4792.62,5598.72 cw(c4792.62,5590.85) 4798.18,5596.42 4803.3,5591.3 cw(c4798.71,5586.72) 4805.19,5586.72 ccw(c4810.35,5586.72) 4806.7,5583.07 ccw(c4810.35,5586.72) 4810.35,5581.56 4812.39,5581.56 ccw(c4812.39,5591.65) 4819.53,5584.52 ; v4(4828,5592) ccw(c4840.59,5592) 4840.59,5579.41 4854.92,5579.41 ccw(c4854.92,5584.41) 4858.46,5580.87 ccw(c4854.92,5584.41) 4859.92,5584.41 4859.92,5584.82 cw(c4865.91,5584.82) 4861.68,5589.05 4867.04,5594.41 cw(c4872.35,5589.08) R184.1@4872.35,5596.61
  Bottom Layer w5: v1(4692,4780.7) ccw(c4720.23,4780.7) 4720.23,4752.47 4817.68,4752.47 ccw(c4817.68,4795) 4860.21,4795 4860.21,5098.85 ccw(c4760.21,5098.85) 4850.81,5141.18 ccw(c4760.21,5098.85) 4830.92,5169.56 4594.27,5406.21 cw(c4671.7,5483.64) 4562.2,5483.64 4562.2,5488.36 cw(c4667.02,5488.36) 4562.2,5488.5 cw(c4667.02,5488.36) 4592.8,5562.38 4594.38,5563.95 cw(c4636.89,5521.44) 4636.89,5581.56 4802.8,5581.56 ccw(c4802.8,5614.8) 4826.31,5591.3 cw(c4828,5589.61) v4(4828,5592)
HUB_D1_P: R183.2 R185.1 R186.2 | length 1464.2
  Top Layer w5: R183.2@4705,4676.08 4706.4,4677.48 v1(4748.6,4677.48) ; R186.2@4792.62,5557.5 ccw(c4792.62,5567.01) 4799.34,5560.29 4805.09,5566.03 ccw(c4803.19,5567.92) 4805.87,5567.92 cw(c4808.55,5567.92) 4806.66,5569.82 4807.34,5570.5 cw(c4810.87,5566.96) 4810.87,5571.96 4812.69,5571.96 cw(c4812.69,5562.57) 4819.33,5569.21 ; v4@4826.31,5562.24 cw(c4833.88,5562.24) 4833.88,5569.81 4855.2,5569.81 cw(c4855.2,5564.59) 4858.89,5568.28 cw(c4855.2,5564.59) 4860.42,5564.59 4860.42,5564.33 ccw(c4866.25,5564.33) 4862.13,5560.21 4867.43,5554.9 ccw(c4872.98,5560.45) R185.1@4872.98,5552.61
  Bottom Layer w5: v1(4748.6,4677.48) 4748.6,4722.47 cw(c4769,4722.47) 4769,4742.87 4819.1,4742.87 ccw(c4819.1,4793.58) 4869.81,4793.58 4869.81,5098.89 ccw(c4760.31,5098.89) 4837.74,5176.32 4601.09,5412.97 cw(c4671.8,5483.68) 4571.8,5483.68 4571.8,5486.38 cw(c4671.8,5486.38) 4601.09,5557.09 cw(c4637,5521.18) 4637,5571.96 4802.82,5571.96 cw(c4802.82,5538.75) 4826.31,5562.24 ccw(c4828.01,5563.94) v4(4828.01,5561.53)
HUB_D2_N: R192.1 R195.2 R196.2 | length 140.2
  Top Layer w5: R196.2@4792.62,5509.5 cw(c4792.62,5500.25) 4799.17,5506.79 4804.27,5501.69 cw(c4800.65,5498.07) 4805.77,5498.07 ccw(c4810.89,5498.07) 4807.27,5494.45 4807.37,5494.35 ccw(c4811.24,5498.21) 4811.24,5492.74 4813.1,5492.74 ccw(c4813.1,5502.72) 4820.15,5495.66 ; v4(4828,5504) cw(c4828,5492.89) 4835.85,5500.75 4838.83,5497.77 ccw(c4848.41,5507.35) 4848.41,5493.8 4854.2,5493.8 ccw(c4854.2,5499.63) 4858.32,5495.51 ccw(c4855.36,5498.46) 4859.54,5498.46 cw(c4863.72,5498.46) 4860.76,5501.42 4866.07,5506.72 cw(c4872.79,5500) R192.1@4872.79,5509.5
  Bottom Layer w5: R195.2@4792.62,5509.5 cw(c4792.62,5500.25) 4799.17,5506.79 4804.27,5501.69 cw(c4800.65,5498.07) 4805.77,5498.07 ccw(c4810.89,5498.07) 4807.27,5494.45 ccw(c4811.38,5498.56) 4810.46,5492.82 ccw(c4811.38,5498.56) 4811.06,5492.75 ccw(c4811.38,5498.56) 4811.38,5492.74 ccw(c4811.38,5506.88) 4821.37,5496.88 4828,5503.51 v4(4828,5504)
HUB_D2_P: R193.1 R194.2 R199.2 | length 146.6
  Top Layer w5: R199.2@4792.62,5468.5 ccw(c4792.62,5478.01) 4799.34,5471.29 4805.03,5476.97 ccw(c4802.97,5479.02) 4805.87,5479.02 cw(c4808.77,5479.02) 4806.72,5481.06 4807.34,5481.69 cw(c4810.87,5478.14) 4810.87,5483.14 4813.69,5483.14 cw(c4813.69,5471.35) v4@4822.03,5479.69 ; v4(4830,5474) ccw(c4830,5485.11) 4837.85,5477.25 4842.27,5481.66 cw(c4848.41,5475.5) 4848.41,5484.2 4854.2,5484.2 cw(c4854.2,5478.38) 4858.32,5482.5 cw(c4855.36,5479.55) 4859.54,5479.55 ccw(c4863.72,5479.55) 4860.76,5476.6 4866.07,5471.29 ccw(c4872.79,5478.01) R193.1@4872.79,5468.5
  Bottom Layer w5: R194.2@4805.02,5476.97 R194.2@4799.34,5471.29 ; R194.2@4805.87,5478.48 cw(c4804.26,5478.48) 4805.87,5478.41 cw(c4804.26,5478.48) 4805.4,5477.34 4805.03,5476.97 ccw(c4802.97,5479.02) 4805.87,5479.02 cw(c4808.77,5479.02) 4806.72,5481.06 cw(c4811.74,5476.04) 4810.41,5483.02 cw(c4811.74,5476.04) 4811.29,5483.13 cw(c4811.74,5476.04) 4811.74,5483.14 4812.1,5483.14 cw(c4812.1,5467.53) 4823.14,5478.57 4826.1,5475.62 ccw(c4830,5479.51) v4(4830,5474) ; R194.2@4799.34,5471.29 cw(c4792.62,5478.01) 4794.86,5468.77 cw(c4792.62,5478.01) R194.2@4792.62,5468.5 ccw(c4792.62,5478.01) R194.2@4799.34,5471.29
INT_ECC_N: J8.6 R43.1 U5.56 | length 2759.7
  Top Layer w8: J8.6@2746,4129 2864,4129 3015.56,3977.44 3015.56,3763.38 ccw(c3115.56,3763.38) 3044.85,3692.67 3515.8,3221.72 3516.31,3221.72 cw(c3445.6,3151.01) 3545.6,3151.01 3545.6,2801.09 ccw(c3645.6,2801.09) 3574.89,2730.38 3796.63,2508.64 cw(c3750.47,2462.48) 3796.67,2508.6 cw(c3750.47,2462.48) 3815.75,2462.48 3815.75,2382.7 3814.73,2349.52 cw(c3775,2350.7) 3814.62,2347.53 cw(c3775,2350.7) 3814.58,2347.09 3814.38,2344.86 3813.73,2337.64 3812.88,2328.21 3811.36,2311.36 ccw(c3825.13,2310.12) 3811.31,2310.59 U5.56@3809.4,2255.08
  Bottom Layer w10: J8.6@2746,4129 3133.38,4129 R43.1@3134.38,4130
INT_PWDN: J8.12 J15.2 R55.1 U5.60 | length 3055.6
  Top Layer w8: v3(3675.6,2490.61) 3675.6,2448.57 ccw(c3763.63,2448.57) 3701.35,2386.35 ; 3701.38,2386.32 3721.16,2366.54 ; 3721.18,2366.52 cw(c3698.23,2343.61) 3730.66,2343.61 U5.60@3730.66,2255.08
  SIG1 w10: J8.12@2746,4429 3272.45,4429 3440.87,4260.57 3600.41,4260.57 v1(3611.45,4271.61) 3611.45,3906.94 cw(c3547.89,3906.94) J15.2@3592.83,3862 cw(c3552.35,3821.52) 3609.6,3821.52 3609.6,2756.03 ccw(c3709.6,2756.03) 3638.89,2685.32 3646.31,2677.9 cw(c3575.6,2607.18) 3675.6,2607.18 v3(3675.6,2490.61)
  Bottom Layer w10: v1(3611.45,4271.61) R55.1@3611.45,4325.14
INT_STTMCHNE_N: J8.8 R44.1 U5.55 | length 2869
  Top Layer w8: J8.8@2746,4229 2864,4229 3107.96,3985.04 3107.96,3777.38 ccw(c3207.96,3777.38) 3137.25,3706.67 3802.25,3041.67 3802.33,3041.67 cw(c3731.62,2970.96) 3831.62,2970.96 3831.62,2337.64 3831.27,2326.2 U5.55@3829.09,2255.08
  Bottom Layer w10: J8.8@2746,4229 3129.38,4229 R44.1@3130.38,4230
INT_SUP_CUR_N: J8.4 R42.1 U5.57 | length 2648.8
  Top Layer w8: J8.4@2746,4029 2864,4029 2918.56,3974.44 2918.56,3718.38 ccw(c3018.56,3718.38) 2947.85,3647.67 3430.15,3165.38 3430.15,3165.33 cw(c3359.44,3094.62) 3459.44,3094.62 3459.44,2847.95 ccw(c3559.44,2847.95) 3488.73,2777.24 3768.79,2497.17 cw(c3698.08,2426.46) 3798.08,2426.46 ccw(c3806.08,2426.46) 3798.08,2426.38 3798.87,2351.01 cw(c3775,2350.7) 3798.82,2349.15 cw(c3775,2350.7) 3798.08,2344.61 3794.43,2330.71 ccw(c3809.4,2326.78) 3794.06,2328.88 3791.75,2311.99 ccw(c3805.44,2310.12) 3791.63,2310.59 U5.57@3789.72,2255.08
  Bottom Layer w10: J8.4@2746,4029 R42.1@3132.38,4029
JTAG_CLK: P1.4 R91.2 U5.28 | length 4057.5
  Top Layer w8: U5.28@3868.46,1751.38 3868.46,1666.54 4188.08,1346.92 cw(c4148.2,1307.04) 4204.6,1307.04 4204.6,1283.68 4204.6,1274.6 ccw(c4304.6,1274.6) 4233.89,1203.89 4355.67,1082.1 cw(c4334.85,1061.28) v1(4364.3,1061.28)
  SIG1 w8: P1.4@1418.49,834.31 1467.9,784.9 ccw(c1538.61,855.61) 1538.61,755.61 3617.18,755.61 ccw(c3617.18,855.61) 3687.89,784.9 3934.98,1031.99 cw(c4005.69,961.28) 4005.69,1061.28 v1(4364.3,1061.28)
  Bottom Layer w20: R91.2@1418.49,756.44 P1.4@1418.49,834.31
JTAG_TDI: P1.8 R89.2 U5.31 | length 3738.9
  Top Layer w8: U5.31@3927.51,1751.38 3927.51,1685.33 ccw(c3949.83,1685.33) 3934.03,1669.57 3946.87,1656.73 ccw(c3965.96,1675.83) 3965.96,1648.82 v1(4041,1648.82)
  SIG1 w8: P1.8@1218.49,834.31 1178.57,834.31 cw(c1178.57,897.01) 1134.24,852.67 cw(c1157.84,876.27) 1124.47,876.27 1124.47,962.07 cw(c1224.47,962.07) 1153.76,1032.78 1163.6,1042.63 cw(c1234.31,971.92) 1234.31,1071.92 3483.79,1071.92 ccw(c3483.79,1171.92) 3554.5,1101.21 3870.12,1416.82 ccw(c3799.41,1487.53) 3899.41,1487.53 3899.41,1524.82 cw(c3999.41,1524.82) 3928.7,1595.53 3952.7,1619.53 cw(c4023.41,1548.82) 4023.41,1648.82 v1(4041,1648.82)
  Bottom Layer w20: R89.2@1218.49,764.31 P1.8@1218.49,834.31
JTAG_TDO: J34.1 P1.6 R88.2 U5.29 | length 5977
  Top Layer w8: U5.29@3888.14,1751.38 3888.14,1670.56 3947,1611.7 ccw(c4017.71,1682.41) 4017.71,1582.41 4029.6,1582.41 cw(c4029.6,1516.81) 4075.98,1563.2 4982.18,657 ccw(c5052.89,727.71) 5052.89,627.71 5611.43,627.71 cw(c5611.43,527.71) 5682.14,598.42 J34.1@5718.99,561.57
  SIG1 w8: P1.6@1318.49,834.31 1407.9,744.9 ccw(c1478.61,815.61) 1478.61,715.61 4563.94,715.61 ccw(c4563.94,815.61) 4634.65,744.9 4762.57,872.82 v1(4764.47,872.82)
  Bottom Layer w20: R88.2@1318.49,764.31 P1.6@1318.49,834.31
JTAG_TMS: P1.2 R86.2 U5.30 | length 3293.7
  Top Layer w8: U5.30@3907.83,1751.38 3907.83,1673.32 3939.58,1641.57 ccw(c3996.04,1698.04) 3996.04,1618.19 4072.9,1618.19 cw(c4072.9,1598.25) v1(4087,1612.35)
  SIG1 w8: P1.2@1518.49,834.31 3375.72,834.31 ccw(c3375.72,934.31) 3446.43,863.6 4057.71,1474.89 ccw(c3987,1545.6) 4087,1545.6 v1(4087,1612.35)
  Bottom Layer w20: R86.2@1518.49,764.31 P1.2@1518.49,834.31
LED0: J28.2 U5.63 | length 3472
  Top Layer w8: v3(3538,2292.68) 3538,2301.1 cw(c3592.6,2301.1) 3592.6,2355.7 3627.6,2355.7 cw(c3627.6,2325.76) 3648.77,2346.93 3666.31,2329.39 cw(c3653.53,2316.61) 3671.61,2316.61 U5.63@3671.61,2255.08
  Bottom Layer w8: J28.2@1368.5,70.98 3086.87,1789.35 ccw(c3016.16,1860.06) 3116.16,1860.06 3116.16,2019.43 cw(c3216.16,2019.43) 3145.45,2090.15 3318.62,2263.32 cw(c3389.33,2192.61) 3389.33,2292.61 3504.5,2292.61 3504.6,2292.71 v3(3538,2292.68)
LED1: J33.2 U5.62 | length 4006.6
  Top Layer w8: v3(3535.6,2384.61) 3620.76,2384.61 cw(c3620.76,2329.98) 3659.37,2368.63 ; 3659.39,2368.61 3683.45,2344.54 cw(c3664.51,2325.61) 3691.29,2325.61 U5.62@3691.29,2255.08
  Bottom Layer w8: J33.2@860.5,78.98 1162.05,380.53 cw(c1232.76,309.82) 1232.76,409.82 1596.58,409.82 ccw(c1596.58,509.82) 1667.29,439.11 2975.31,1747.13 ccw(c2904.6,1817.84) 3004.6,1817.84 3004.6,1971.13 cw(c3104.6,1971.13) 3033.89,2041.84 3329.6,2337.55 3363.13,2371.08 cw(c3412.38,2321.82) 3412.38,2391.48 3519,2391.48 cw(c3519,2368.01) v3(3535.6,2384.61)
LED2: J38.2 U5.61 | length 4582.9
  Top Layer w8: v3(3573.6,2500.61) 3573.6,2483.1 3700.6,2356.1 cw(c3675.54,2331.05) 3710.98,2331.05 U5.61@3710.98,2255.08
  Bottom Layer w8: J38.2@374.5,81.98 826.54,534.03 cw(c897.26,463.32) 897.26,563.32 1605.83,563.32 ccw(c1605.83,663.32) 1676.54,592.6 2903.59,1819.65 ccw(c2832.88,1890.36) 2932.88,1890.36 2932.88,1989.99 cw(c3032.88,1989.99) 2962.17,2060.7 3335.79,2434.32 cw(c3406.5,2363.61) 3406.5,2463.61 3495.18,2463.61 ccw(c3495.18,2563.61) 3565.89,2492.9 v3(3573.6,2500.61)
MCU_VCC: C10.1 C11.1 C12.1 C21.1 C22.1 C23.1 C112.1 C113.1 C114.1 C129.1 R4.2 R8.2 R36.2 R38.2 R40.2 R41.2 R49.2 R50.2 R52.2 R53.2 R62.2 R63.2 R64.2 R65.2 R66.2 R67.2 R75.1 R76.1 R174.2 R175.2 R178.2 R179.2 R198.2 U1.11 U1.15 U1.40 U4.18 U4.50 U13.3 U14.3 U14.6 U14.8 U14.25 U14.26 | length 2588.9
  Top Layer w9: 5008.25,5676.98 5018.82,5676.98 ; U14.6@5065.88,5647.99 5066.3,5648.41 5066.3,5671.46 5061.03,5676.73 5035.78,5676.73 ; C11.1@5091.15,4861.48 5168.22,4861.48 5176,4853.7 5176,4789.7 5169.04,4782.74 U1.15@5142.77,4782.74 ; U14.3@5124.94,5647.99 v1@5124.94,5690.64 ; U14.25@5189.32,5484.41 5199.52,5484.41 5224.41,5459.52 v1(5226.43,5459.52) ; U14.26@5189.9,5504.29 5212.89,5504.29 v1(5223.77,5515.18) ; U1.40@5489.22,4900.85 v1(5532.85,4900.85) ; 5018.82,5676.98 5029.39,5676.98 5029.64,5676.73 5035.78,5676.73 ; 5018.82,5676.98 5026.51,5669.29 U14.8@5026.51,5647.99 5026.93,5648.41 5026.93,5668.3 5027.14,5668.1 5035.78,5676.73
  Top Layer w10: v1(4118.83,5094.61) U4.18@4118.83,5161.23 ; 4256.63,4577.61 U4.50@4256.63,4631.7
  Top Layer w15: C129.1@4925.63,5676.98 5008.25,5676.98
  Top Layer w20: v1(4007.6,4195.61) 4054.1,4195.61 R41.2@4055.6,4194.11 ; v1(4070.38,4111.55) 4101.5,4111.55 4101.75,4111.8 4115.17,4111.8 R38.2@4116.98,4113.61 ; v1(4088.6,4462.61) R66.2@4088.6,4506.61 ; v1(4239.6,4463.61) 4239.1,4464.11 4239.1,4506.61 4242.54,4506.61 4244.35,4508.42 4244.35,4511.85 4256.63,4524.14 4256.63,4577.61 ; 4891.01,5676.98 C129.1@4925.63,5676.98 ; R179.2@4989,5334.08 4990.81,5332.27 4990.81,5308.3 v1(5009.12,5289.99) ; R8.2@5070.41,5138.14 v1(5070.41,5172.52) ; v1(5072.8,4817.7) 5072.8,4818.78 5083.11,4829.08 5083.11,4858.58 C11.1@5084.22,4859.7 ; R178.2@5223.62,5729 5225.43,5727.19 5258.15,5727.19 5273.72,5711.62 5273.72,5711.18 v1(5275.24,5711.18)
  Top Layer w22: v1(3400.32,4435.84) 3400.7,4436.22 3445.71,4436.22 R40.2@3448.6,4439.11 ; v1(3461.6,4307.61) 3461.98,4307.99 3461.98,4308.55 3500.04,4346.61 R36.2@3503.98,4346.61 ; v1(3953.6,5527.76) 3954.35,5527.76 3997.31,5484.8 3997.31,5482.83 C21.1@4034.54,5445.61 ; v1(3956.6,5367.67) C21.1@4034.54,5445.61 ; C21.1@4036.5,5445.61 C21.1@4034.54,5445.61 ; v1(4100.6,5306.61) C22.1@4148.17,5306.61 ; v1(4102.3,5262.61) 4102.84,5262.61 4105.03,5260.42 4147.35,5260.42 C23.1@4148.17,5259.61 ; 4891.01,5676.98 v1(4848.25,5676.98) 4834.63,5690.61 4834.63,5747.61 v1(4856.63,5769.61) 4989.63,5769.61 5017.63,5797.61 R198.2@5022.63,5797.61
  Bottom Layer w15: C12.1@5489.62,4905.7 5528,4905.7 v1(5532.85,4900.85)
  Bottom Layer w20: v1(4118.83,5094.61) 4118.83,5118.28 4165.29,5164.73 R76.1@4169.23,5164.73 ; v1(4927,5015.7) 4958,5015.7 4968,5025.7 R4.2@5019,5025.7 ; v1(4995.6,4898.08) 4995.6,4831.77 ccw(c5012.67,4831.77) C10.1@5000.6,4819.7 ; C10.1@5000,4820.79 5003.09,4817.7 v1(5072.8,4817.7) ; R75.1@5366.62,4295.61 5370.56,4295.61 5402.25,4327.3 5402.25,4331.23 v1(5403.02,4332)
  Bottom Layer w22: R62.2@4397.6,5482.23 v1(4397.6,5528.61) ; R63.2@4441.6,5482.23 v1(4441.6,5526.61) ; R64.2@4484.6,5482.23 v1(4484.6,5526.61) ; v1(4525.6,5526.61) 4528.6,5523.61 R65.2@4528.6,5482.23 ; v1(4484.6,5526.61) ccw(c4483.6,5526.61) 4483.6,5527.61 v1(4484.6,5526.61)
  other v1: 4791.66,5078.25 4795.6,5133.5 3941.6,5415.61 3941.6,5469.61 5122,5692.7 4057.6,5744.1 4012.6,5788.61 4066.6,5791.61
MDC: J43.3 R11.1 R48.1 R54.1 U3.3 U5.54 | length 2210.2
  Top Layer w6: U3.3@4183.49,4224.89 4183.49,4213.72 ccw(c4209.6,4213.72) v1(4209.6,4187.61)
  Top Layer w8: U5.54@3848.77,2255.08 3848.77,2632.36 cw(c3948.77,2632.36) 3878.06,2703.07 3949.53,2774.54 ccw(c3896.75,2827.31) 3971.39,2827.31 R11.1@3971.39,2852.9 3954.58,2869.71 cw(c4012.47,2927.61) 3930.6,2927.61 3930.6,2933.18 cw(c4030.6,2933.18) 3959.89,3003.9 4070.31,3114.32 ccw(c3999.6,3185.03) 4099.6,3185.03 J43.3@4099.6,3876.61 4162.31,3939.32 ccw(c4091.6,4010.03) 4191.6,4010.03 4191.6,4064.61 cw(c4284.84,4064.61) 4218.91,4130.54 R48.1@4230.1,4141.73 4230.1,4167.11 ccw(c4209.6,4167.11) v1(4209.6,4187.61)
  Bottom Layer w8: R54.1@4169.71,4215.05 4188.35,4196.41 ccw(c4209.6,4217.66) v1(4209.6,4187.61)
MDC_1: J1.8 J2.31 | length 769.1
  Bottom Layer w10: J2.31@7833.6,1634.61 8099.99,1634.61 8422.39,1312.2 J1.8@8469.11,1312.2
MDC_2: J22.8
MDC_CS: J4.8 R11.2 | length 3629.3
  Top Layer w8: R11.2@3971.39,2900.15 3971.39,2900.97 cw(c4071.39,2900.97) 4000.68,2971.69 v3(4018.6,2989.61) ; v3(4536.62,2031.61) 4537.8,2030.42 ccw(c4608.51,2101.13) 4540.24,2028.07 ccw(c4608.51,2101.13) 4608.51,2001.13 4626.65,2001.13 cw(c4626.65,1901.13) 4697.36,1971.84 5404.34,1264.86 ccw(c5446,1306.52) 5446,1247.61 cw(c5446,1180.98) 5493.11,1228.09 5628.93,1092.27 ccw(c5699.64,1162.98) 5699.64,1062.98 6109.64,1062.98 cw(c6109.64,1003.65) v3(6151.6,1045.61)
  Bottom Layer w8: v3(4018.6,2989.61) 4022.78,2985.43 ccw(c4093.49,3056.14) 4093.49,2956.14 4206.64,2956.14 cw(c4206.64,2856.14) 4277.35,2926.85 4289.6,2914.61 ccw(c4349.95,2974.96) 4349.95,2889.61 4377.32,2889.61 cw(c4377.32,2833.4) 4417.06,2873.14 4568.6,2721.61 cw(c4497.89,2650.9) 4597.89,2650.9 4597.89,2410.8 cw(c4511.35,2410.8) 4572.54,2349.61 4565.91,2342.97 ccw(c4636.62,2272.26) 4536.62,2272.26 v3(4536.62,2031.61) ; v3(6151.6,1045.61) cw(c6181.03,1016.18) 6181.03,1057.8 J4.8@6308.86,1057.8
MDC_LP: J19.8
MDC_MSP: R54.2 R66.1 U3.6 U4.46 | length 449.7
  Top Layer w6: v1(4169.71,4305.61) cw(c4169.71,4291.83) 4183.49,4291.83 U3.6@4183.49,4260.32
  Top Layer w8: R66.1@4135.84,4506.61 4140.42,4502.03 cw(c4069.71,4431.32) 4169.71,4431.32 v1(4169.71,4305.61)
  Top Layer w10: R66.1@4135.84,4506.61 4177.89,4548.65 U4.46@4177.89,4631.7
  Bottom Layer w8: R54.2@4169.71,4262.29 v1(4169.71,4305.61)
MDIO: J43.2 R12.1 R56.1 R85.2 U3.4 U5.53 | length 2234.9
  Top Layer w6: U3.4@4197.27,4224.89 4244.07,4224.89 cw(c4244.07,4219.36) R56.1@4249.6,4219.36
  Top Layer w8: U5.53@3868.46,2255.08 3868.46,2461.73 cw(c3968.46,2461.73) 3897.75,2532.45 4071.22,2705.92 ccw(c4000.51,2776.63) 4100.51,2776.63 R12.1@4100.51,2858.98 4075.02,2884.47 cw(c4129.16,2938.61) 4052.6,2938.61 4052.6,2941.18 cw(c4152.6,2941.18) 4081.89,3011.9 4170.31,3100.32 ccw(c4099.6,3171.03) 4199.6,3171.03 J43.2@4199.6,3876.61 4280.31,3957.32 ccw(c4209.6,4028.03) 4309.6,4028.03 4309.6,4067.61 ccw(c4219.98,4067.61) 4283.35,4130.98 R85.2@4273.1,4141.23 4273.1,4162.63 ccw(c4192.86,4162.63) R56.1@4249.62,4219.34
MDIO_1: J1.10 J2.33 | length 957.2
  Bottom Layer w10: J2.33@7833.6,1734.61 7788.24,1689.25 7788.24,1615.82 7824.1,1579.96 7833.27,1579.96 7833.42,1579.96 cw(c7833.6,1534.61) 7833.78,1579.96 7833.93,1579.96 8104.04,1579.96 8403.29,1280.71 J1.10@8469.11,1280.71
MDIO_2: J22.10
MDIO_CS: J4.10 R12.2 | length 3550.9
  Top Layer w8: R12.2@4100.51,2900.15 4100.51,2932.48 cw(c4199.68,2932.48) v3(4129.55,3002.61) ; v3(4568.6,2048.94) ccw(c4611.33,2091.67) 4611.33,2031.24 4628.75,2031.24 cw(c4620.18,1931.61) 4690.89,2002.32 5417.48,1275.73 ccw(c5444.6,1302.84) 5444.6,1264.49 cw(c5444.6,1167.2) 5513.4,1236 5656.6,1092.79 ccw(c5682.02,1118.22) 5682.02,1082.26 v3(6156.02,1082.26)
  Bottom Layer w8: v3(4129.55,3002.61) 4326.04,3002.61 cw(c4326.04,2902.61) 4396.75,2973.32 4604.31,2765.76 cw(c4533.6,2695.05) 4633.6,2695.05 4633.6,2380.48 cw(c4551.66,2380.48) 4609.6,2322.54 4597.89,2310.83 ccw(c4668.6,2240.12) 4568.6,2240.12 v3(4568.6,2048.94) ; v3(6156.02,1082.26) cw(c6172.99,1065.29) 6172.99,1089.29 J4.10@6308.86,1089.29
MDIO_LP: J19.10
MDIO_MSP: R56.2 R67.1 U3.5 U4.47 | length 441.5
  Top Layer w6: U3.5@4197.27,4260.32 4234.43,4260.32 ccw(c4234.43,4281.78) R56.2@4249.6,4266.61
  Top Layer w8: R67.1@4191.35,4506.61 4191.35,4382.61 4191.35,4366.27 ccw(c4291.35,4366.27) 4191.35,4366.22 ccw(c4291.35,4366.27) 4214.29,4302.54 ccw(c4291.35,4366.27) 4220.64,4295.56 R56.2@4249.6,4266.61
  Top Layer w10: R67.1@4191.35,4506.61 4197.57,4512.83 U4.47@4197.57,4631.7
MSP_XIN: C15.1 U4.69 Y2.3 | length 203.6
  Top Layer w10: U4.69@4531.24,4866.94 4597.38,4866.94 4605.93,4875.48 4661.02,4875.48 Y2.3@4665.32,4871.17 Y2.3@4669.26,4871.17 ; C15.1@4696.17,4823.79 C15.1@4697.35,4822.61
  Top Layer w20: Y2.3@4669.26,4871.17 4696.17,4844.26 C15.1@4696.17,4823.79
MSP_XOUT: R68.2 U4.70 | length 272.3
  Top Layer w10: U4.70@4531.24,4886.62 4583.06,4886.62 4615.6,4919.16 4615.6,4999.61 4627.65,5011.66 4657.72,5011.66 4673.78,4995.61 R68.2@4697.98,4995.61
NetC4_1: C4.1 R7.2 Y1.1 | length 207.6
  Top Layer w9: C4.1@5232.1,5279.17 5232.2,5279.27 5232.2,5307.2 v1(5252.6,5327.61) 5254.25,5325.95 5269.01,5325.95 5288.17,5306.79 5288.17,5261.98 Y1.1@5291.54,5258.61
  Bottom Layer w9: R7.2@5232.1,5279.17 5232.1,5307.11 v1(5252.6,5327.61)
NetC6_1: C6.1 U1.55 | length 133.3
  Top Layer w9: v1(5331.6,5156.61) 5331.6,5113.09 5345.52,5099.17 U1.55@5345.52,5083.92
  Bottom Layer w15: C6.1@5315.99,5108.2 5315.99,5141 v1(5331.6,5156.61)
NetC7_1: C7.1 U1.17 | length 91
  Top Layer w9: U1.17@5168.32,4737.47 5168.32,4696.38 v1(5170,4694.7)
  Bottom Layer w15: v1(5170,4694.7) 5171,4694.7 C7.1@5171,4741.2
NetC13_1: C13.1 R40.1 U2.7 U2.8 | length 134.6
  Top Layer w6: R40.1@3448.6,4502.1 3464.25,4486.45 3499.42,4486.45 C13.1@3507.2,4494.23 3513.2,4488.23 U2.8@3557.26,4488.23 U2.7@3571.04,4488.23
NetC14_1: C14.1 R41.1 U3.7 U3.8 | length 13.8
  Top Layer w6: U3.8@4155.93,4260.32 U3.7@4169.71,4260.32
NetC16_1: C16.1 R68.1 Y2.1 | length 160.2
  Top Layer w10: R68.1@4745.22,4995.61 4787.1,4995.61 4789.78,4992.93 4789.78,4972.01 4759.81,4942.04 Y2.1@4755.87,4942.04
  Bottom Layer w10: C16.1@4745.22,4995.61 v1(4792.46,4995.61)
NetC17_1: C17.1 U4.67 | length 170.7
  Top Layer w10: U4.67@4531.24,4827.57 4531.58,4827.91 4592.06,4827.91 4607.84,4843.7 v1(4609.32,4843.7)
  Bottom Layer w10: C17.1@4539.09,4881.61 4551.37,4869.34 4566.42,4869.34 4592.06,4843.7 v1(4609.32,4843.7)
NetC18_1: C18.1 U4.20 | length 128
  Top Layer w10: v1(4036.6,5207.61) 4056.91,5207.61 4078.56,5185.95 4078.56,5185.26 4079.46,5184.36 U4.20@4079.46,5161.23
  Bottom Layer w10: v1(4036.6,5207.61) 4071.6,5207.61 4079.6,5215.61 C18.1@4083.6,5211.61
NetC20_1: C20.1 U4.66 | length 155
  Top Layer w10: U4.66@4531.24,4807.88 v1(4609.32,4807.88)
  Bottom Layer w10: C20.1@4538.76,4823.24 4577.34,4823.24 4591.92,4808.66 4608.54,4808.66 v1(4609.32,4807.88)
NetC24_1: C24.1 R76.2 U4.11 | length 175
  Top Layer w10: v1(4255.83,5216.63) 4256.61,5215.85 U4.11@4256.63,5161.23
  Bottom Layer w20: R76.2@4216.47,5164.73 4220.41,5164.73 4255.83,5200.16 v1(4255.83,5216.63) 4255.83,5253.69 4249.92,5259.61 C24.1@4246.62,5259.61
NetC47_1: C47.1 R80.1 | length 68.2
  Bottom Layer w8: R80.1@187.29,775.18 187.29,709.8 C47.1@189.29,707.8
NetC48_1: C48.1 R77.1 R81.1 XTAL1.2 | length 383
  Bottom Layer w8: C48.1@3835.97,1388.79 3882.12,1388.79 cw(c3882.12,1353.65) XTAL1.2@3906.97,1378.5
  Bottom Layer w10: XTAL1.2@3907.26,1356.8 3907.26,1265.51 3916.97,1255.8 R81.1@4007.35,1255.8
  Bottom Layer w15: XTAL1.2@3903.96,1388.79 XTAL1.2@3906.97,1391.8 ; R77.1@3906.97,1466.31 XTAL1.2@3906.97,1391.8 ; XTAL1.2@3907.26,1356.8 3906.97,1357.09 3906.97,1378.5 XTAL1.2@3906.97,1391.8
NetC49_1: C49.1 R78.1 R81.2 R82.1 | length 353.6
  Bottom Layer w10: R81.2@4054.59,1255.8 4074.59,1235.8 4171.97,1235.8 4209.97,1273.8 C49.1@4209.97,1322.8 R78.1@4209.97,1383.8 4209.97,1447.3 R82.1@4209.47,1447.8
NetC51_2: C51.2 R83.1 U5.15 | length 214.4
  Top Layer w8: v1(3385.57,1853.23) 3426.41,1853.23 3426.41,1857.17 3444.52,1875.27 U5.15@3547.71,1875.27
  Bottom Layer w8: v1(3385.57,1853.23) R83.1@3426.41,1853.23
NetC54_1: C54.1 C69.1 C72.1 C79.1 R126.2 | length 504.7
  Bottom Layer w20: C54.1@1623.1,1751.61 C54.1@1620.5,1749 1619.94,1749.56 1619.94,1805.44 R126.2@1619.38,1806 1619.38,1851.92 1640.98,1873.53 C69.1@1641.97,1873.53 1639.23,1876.27 1639.23,2037.26 C72.1@1636.5,2040 1633.23,2043.26 C79.1@1633.23,2231.41 ; C79.1@1629.97,2231.68 C79.1@1633.23,2228.41
NetC54_2: C54.2 T1.1 | length 144
  Top Layer w20: T1.1@1419.86,1741.7 T1.1@1419.86,1741.7 1508.05,1741.65 v1(1508.09,1741.61)
  Bottom Layer w20: v1(1508.09,1741.61) 1542.38,1741.61 1553.64,1752.87 C54.2@1557.5,1749
NetC56_1: C56.1 U6.4 | length 73.4
  Top Layer w10: U6.4@652.03,5825.18 655.72,5825.18 655.8,5825.26 655.8,5838.31
  Top Layer w15: 655.8,5838.31 681.68,5864.19 C56.1@701.6,5864.19
NetC56_2: C56.2 L1.1 U6.3 U6.12 | length 125.8
  Top Layer w10: U6.12@616.6,5767.58 616.6,5798.43 623.67,5805.5 U6.3@652.03,5805.5 694.08,5805.5 701.6,5813.01 C56.2@701.6,5816.95
NetC62_1: C62.1 U6.5 | length 61
  Top Layer w10: U6.5@636.28,5853.72 636.28,5886.66
  Top Layer w20: 637.88,5886.66 637.88,5910.89 C62.1@640.6,5913.61
NetC69_2: C69.2 T1.4 | length 166.7
  Top Layer w20: T1.4@1419.86,1891.7 1511.01,1891.7 1514.57,1888.14 v1(1515.65,1888.14)
  Bottom Layer w20: v1(1515.65,1888.14) 1530.31,1873.48 1578.93,1873.48 C69.2@1578.98,1873.53
NetC72_2: C72.2 T1.7 | length 214.2
  Top Layer w20: T1.7@1419.86,2041.7 1510.88,2041.7 1512.58,2040 v1(1513.66,2040) ; T1.7@1424.59,2041.61 1484.43,2041.61
  Bottom Layer w20: v1(1513.66,2040) C72.2@1573.5,2040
